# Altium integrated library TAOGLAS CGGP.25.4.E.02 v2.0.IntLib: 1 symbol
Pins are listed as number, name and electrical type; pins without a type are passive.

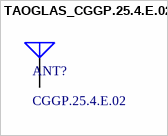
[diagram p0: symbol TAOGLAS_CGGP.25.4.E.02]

## TAOGLAS_CGGP.25.4.E.02
designator ANT?, comment CGGP.25.4.E.02
GPS/GLONASS/GALILEO Dual-Band Patch Antenna 25*25*4mm; ComponentLibStatus: Created; MFG: Taoglas; Temp_High: +85C; Temp_Low: -40C
footprint TAOGLAS_CGGP.25.4.E.02 (GPS/GLONASS/GALILEO Dual-Band Patch Antenna 25*25*4mm)
pins: 1 A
